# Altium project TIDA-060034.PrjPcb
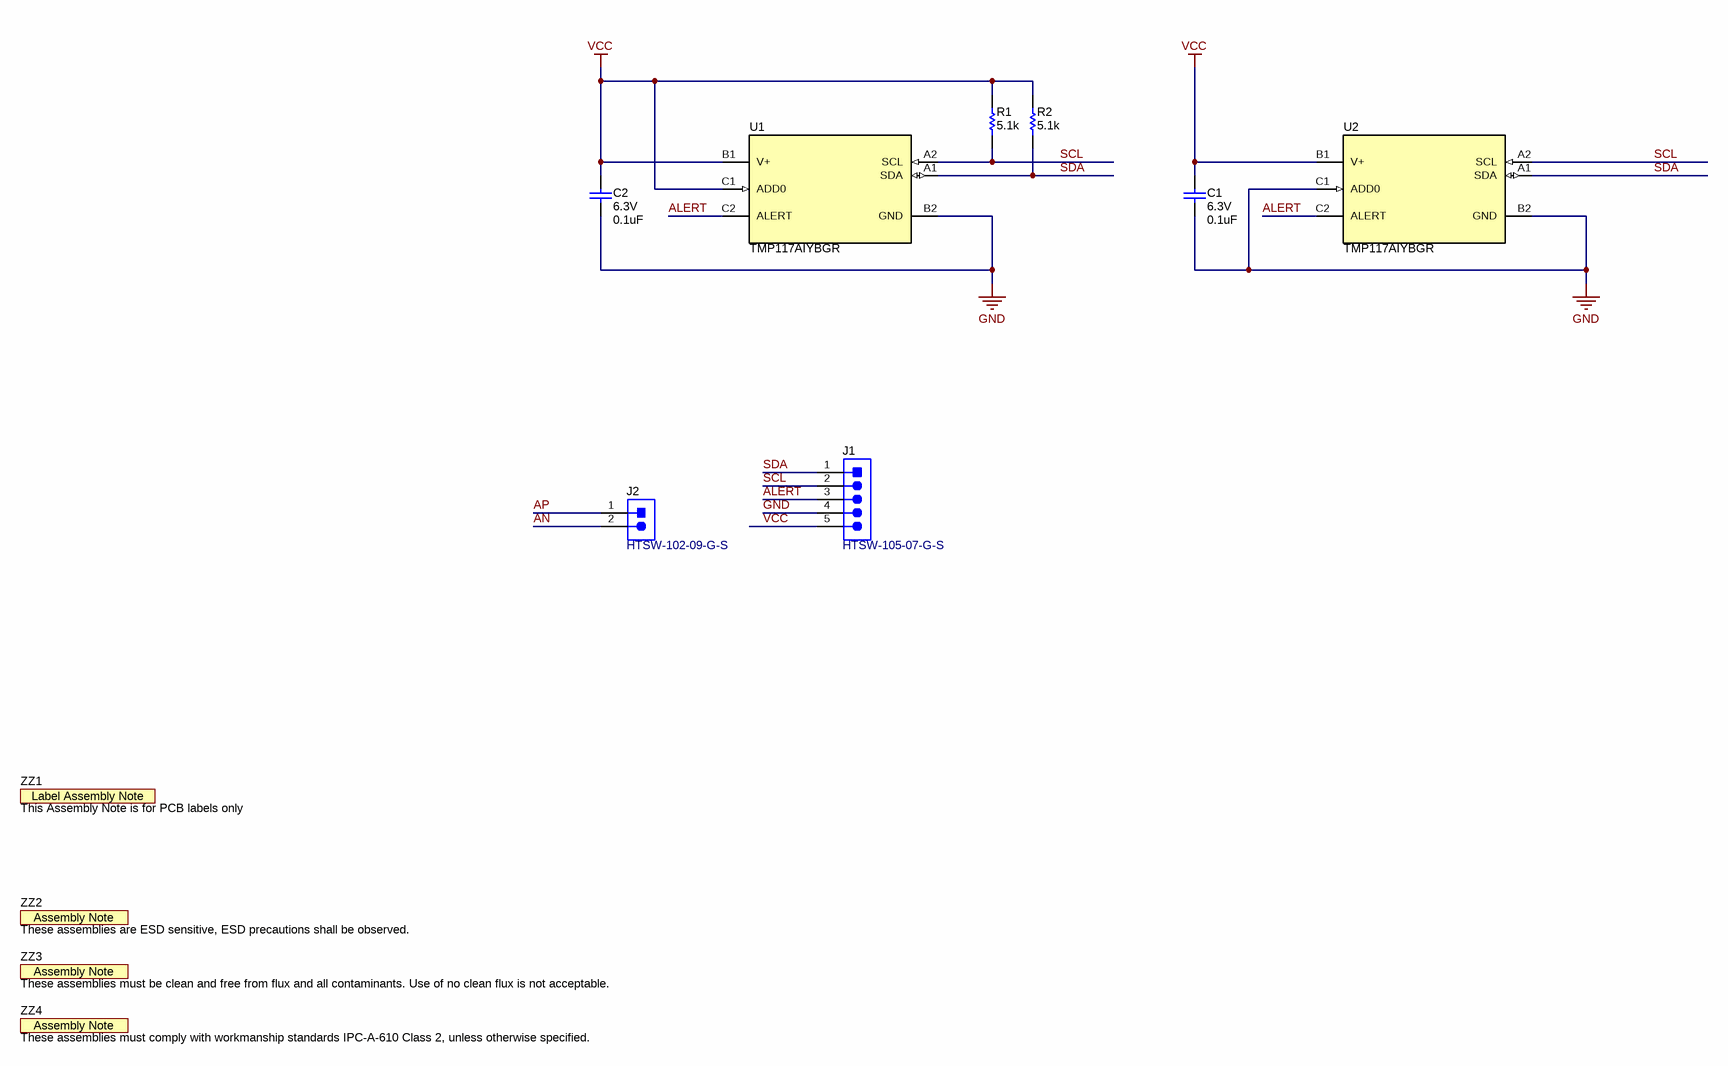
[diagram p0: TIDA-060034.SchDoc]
TID: TIDA-060034; TechSupport: http://www.ti.com/support; SCH_Rev: A; PRJ_Title: TMP117_Hearable_design; PRJ_Number: TIDA-060034; PRJ_Engineer: David Vaseliou; PRJ_Customer: Public Release; PCB_Rev: A; PCB_Layout: David Vaseliou; CopyrightYear: 2020
1 sheet, 12 parts. Net scope: global (net labels, ports and power ports of the same name join across sheets).
Board file: TIDA-060034.PcbDoc

## Sheet TIDA-060034.SchDoc: Hearables Body Temperature Monitor Flex PCB
size 431 x 279 mm; Date: Not shown in title block; ApprovedBy: Not shown in title block; CheckedBy: Not shown in title block; Author: Not shown in title block; CompanyName: Not shown in title block; DrawnBy: David Vaseliou; Engineer: Not shown in title block; Organization: Not shown in title block; Address1: Not shown in title block; Address2: Not shown in title block; Address3: Not shown in title block; Address4: Not shown in title block; DocumentNumber: 2; Revision: Use project parameter SCH_Rev; SheetNumber: 1; SheetTotal: 1; PageSetup: Record=PageOptions¦CenterHorizontal=True¦CenterVertical=True¦PrintScale=1.00¦XCorrection=1.00¦YCorrection=1.00¦PrintKind=0¦BorderSize=5000000¦LeftOffset=0¦BottomOffset=0¦Orientation=2¦PaperLength=1000¦PaperWidth=1000¦Scale=100¦PaperSource=15¦PrintQuality=600¦MediaType=1¦DitherType=10¦PaperKind=Letter¦PrintScaleMode=1

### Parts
C1  VDC_V: 6.3V  ValueDisplayed: 0.1uF  [01005]  (hidden comment: GRM022R60J104ME15)
C2  VDC_V: 6.3V  ValueDisplayed: 0.1uF  [01005]  (hidden comment: GRM022R60J104ME15)
J1  HTSW-105-07-G-S  [Samtec_HTSW-105-07-G-S]
J2  HTSW-102-09-G-S  [Samtec_HTSW-102-09-x-S]
R1  ValueDisplayed: 5.1k  [0201]  (hidden comment: RC0201JR-075K1L)
R2  ValueDisplayed: 5.1k  [0201]  (hidden comment: RC0201JR-075K1L)
U1  TMP117AIYBGR  [YBG0006AJAP]
U2  TMP117AIYBGR  [YBG0006AJAP]
ZZ1  This Assembly Note is for PCB labels only  [AssemblyNoteLabel]  (no BOM)
ZZ2  These assemblies are ESD sensitive, ESD precautions shall be observed.  [AssemblyNote]  (no BOM)
ZZ3  These assemblies must be clean and free from flux and all contaminants. Use of no clean flux is not acceptable.  [AssemblyNote]  (no BOM)
ZZ4  These assemblies must comply with workmanship standards IPC-A-610 Class 2, unless otherwise specified.  [AssemblyNote]  (no BOM)

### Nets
GND: C1.2 C2.2 J1.4 U1.B2(GND) U2.B2(GND) U2.C1(ADD0)
VCC: C1.1 C2.1 J1.5 R1.2 R2.2 U1.B1(V+) U1.C1(ADD0) U2.B1(V+)
ALERT: J1.3 U1.C2(ALERT) U2.C2(ALERT)
AN: J2.2
AP: J2.1
SCL: J1.2 R1.1 U1.A2(SCL) U2.A2(SCL)
SDA: J1.1 R2.1 U1.A1(SDA) U2.A1(SDA)

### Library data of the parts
C1 C2 = CMP-0009442-2: CAP, CERM, 0.1 uF, 6.3 V, +/- 20%, X5R, 01005; Manufacturer: MuRata; TaMin_C: -55°C; Polarized: N; Value1: Unknown; U/M: EA; Value: 0.1uF; TaMax_C: 85°C; SizeZ_mm: 0.2; SizeX_mm: 0.4; SizeArea_mm2: 0.08; Cap_F: 100nF; AEC Category: Q200; SizeAreaWB_mm2: 1.68
J1 = CMP-0075485-1: Header, 100mil, 5x1, Gold, TH; Manufacturer: Samtec; Green_REACh: Passed; CT: False; Green_Lifecycle: Active; CNHeader: True
J2 = CMP-0075626-1: Header, 100mil, 2x1, Gold, TH; Manufacturer: Samtec; Pitch_mm: 2.54; Gender: Male; Cert_CSA: Y; CT: False; Row_Count: 1
R1 R2 = CMP-0027144-1: RES, 5.1 k, 5%, 0.05 W, 0201; Manufacturer: Yageo America; Power_W: 50mW; TempCo: 200 ppm/C; Value_Code: 5k10; U/M: EA; Value: 5.1k; EIA_Code: E24; SizeX_mm: 0.6; SizeY_mm: 0.3; SizeZ_mm: 0.26; Value2: 0.05W; SizeArea_mm2: 0.18; AEC Qualified: N; VDC_V: 25V; AEC Category: Q200
U1 U2 = CMP-0860099-1: ±0.1°C accurate digital temperature sensor with integrated NV memory, YBG0006AJAP (DSBGA-6); Alternate Manufacturer: Texas Instruments; Alternate PartNumber: TMP117AIYBGT; SizeArea_mm2: 2.0049; SizeZ_mm: 0.5; SizeY_mm: 1.63; SizeX_mm: 1.23; AEC Qualified: N; SizeAreaWB_mm2: 5.8649; AEC Category: Q200; CompType: IC; Rating: Catalog
ZZ1 = CMP-0003616-3
ZZ2 = CMP-0077236-1
ZZ3 = CMP-0077237-1
ZZ4 = CMP-0077238-1

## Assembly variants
001: not fitted J1 J2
